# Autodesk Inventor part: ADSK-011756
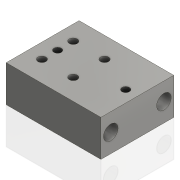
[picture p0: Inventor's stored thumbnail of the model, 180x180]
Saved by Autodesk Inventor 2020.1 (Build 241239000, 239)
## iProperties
Created: 1999-11
Part Number: ADSK-011756
Material: Aluminum
Document SubType Name: Modeling
Designer: sspink
Density: 2.71 g/cm^3
Appearance: Steel
Mass: 1502.63 g
Surface Area: 704.066 cm^2
Volume: 554.478 cm^3
Control State: 0
Master: False
Checked Out: False
Shininess: 0.0
Length Units: 11269
Angle Units: 11279
Time Units: 11290
Mass Units: 11283
Length Display Precision: 3
Angle Display Precision: 2
Compacted: True
Dimensions: 130x50x100 mm
Mass: 1,503 kg
Density: 0.0
Volumn: 0.0
Area: 0.0
PropertySet Name: Model Information
Author: sspink
Revision Number: -
Title: ADSK-011756
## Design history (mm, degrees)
node "Solide1"
  node "Extrusion1" dims "d2" = 100 (= F), "d3" = 0
  node "Hole2" dims "d26" = 6.4008, "d27" = 9.525, "d28" = 6.35, "d29" = 60 deg, "d30" = 25 (= 0.5 x L), "d31" = 118 deg
  node "Hole3" dims "d32" = 6.6, "d33" = 11, "d34" = 6.8, "d35" = 60 deg, "d36" = 12.7, "d37" = 118 deg, "d82" = 6
  node "Extrusion2" dims "d61" = 57.15, "d62" = 0
  node "Hole7" dims "d75" = 10.106, "d76" = 9.525, "d77" = 6.35, "d78" = 60 deg, "d79" = 32.3, "d80" = 118 deg, "d83" = 24
sketch "Sketch1"
  geometry: L1 (-101.574, -4.517)-(28.426, -4.517) reference; L2 (28.426, -4.517)-(28.426, 45.483) reference; L3 (28.426, 45.483)-(-101.574, 45.483); L4 (-101.574, 45.483)-(-101.574, -4.517)
  constraints: 8 end point, 2 horizontal, 2 parallel, 1 perpendicular, 1 vertical
  dimensions: "d0" = 130 distance of L1.start L1.end (= A + Travel); "d1" = 50 distance of L1.end L2.end (= L)
sketch "Sketch3"
  geometry: L1 (0, 0)-(0, 100) reference; L2 (130, 0)-(130, 100) reference; L3 (0, 50)-(130, 50); 4 further points
  constraints: 2 end point, 2 midpoint
  dimensions: "d18" = 20.5 distance from line of point (20.5, 71.5) L1 (= B); "d19" = 20.5 distance from line of point (20.5, 28.5) L1 (= B); "d20" = 43 distance of point (63.5, 28.5) point (20.5, 28.5) (= C); "d21" = 43 distance of point (20.5, 71.5) point (63.5, 71.5) (= C); "d22" = 21.5 distance from line of point (63.5, 71.5) L3 (= 0.5 x C); "d23" = 21.5 distance from line of L3 point (63.5, 28.5) (= 0.5 x C); "d24" = 21.5 distance from line of L3 point (20.5, 28.5) (= 0.5 x C); "d25" = 21.5 distance from line of point (20.5, 71.5) L3 (= 0.5 x C)
node "Corps solides"
node "Corps surfaciques"
sketch "Sketch4"
  geometry: C1 r 3.2 at (20.5, -28.5) reference; C2 r 3.2 at (63.5, -28.5) reference; C3 r 3.2 at (63.5, -71.5) reference; C4 r 3.2 at (20.5, -71.5) reference; 4 further points
  constraints: 4 coincident
sketch "Sketch7"
  geometry: L1 (0, 50)-(100, 50) reference; L2 (0, 0)-(100, 0) reference; L3 (50, 50)-(50, 0); C1 r 10 at (86.5, 25.4); C2 r 10 at (13.5, 25.4)
  constraints: 2 centre point, 2 end point, 2 midpoint, 1 equal radius, 1 horizontal alignment
  dimensions: "d58" = 36.5 distance from line of L3 C2.centre (= 0.5 x W0); "d59" = 36.5 distance from line of L3 C1.centre (= 0.5 x W0); "d60" = 20 diameter of C2 (= X); "d81" = 25.4 distance from line of C2.centre L2 (= D)
sketch "Sketch9"
  geometry: L1 (130, 0)-(130, -100) reference; L2 (0, 0)-(0, -100) reference; L3 (0, -50)-(130, -50); 2 further points
  constraints: 2 end point, 2 midpoint, 2 point on line
  dimensions: "d73" = 20.5 distance from line of point (20.5, -50) L2 (= N_1); "d74" = 16 distance from line of L1 point (114, -50) (= R)
other parameters: "A" = 54 [user parameter; used in 1 equation term], "B" = 20.5 [user parameter; used in 2 equation terms], "C" = 43 [user parameter; used in 6 equation terms], "D" = 25.4 [user parameter; used in 1 equation term], "E0" = 25.4 [user parameter], "G" = 25 [user parameter], "H" = 25 [user parameter], "J0" = 25 [user parameter], "K_1" = 25 [user parameter], "L" = 50 [user parameter; used in 2 equation terms], "M" = 25.4 [user parameter], "N_1" = 20.5 [user parameter; used in 1 equation term], "O" = 25 [user parameter], "P" = 25 [user parameter], "Q" = 6 [user parameter], "R" = 16 [user parameter; used in 1 equation term], "S" = 25 [user parameter], "T" = 25 [user parameter], "U" = 25 [user parameter], "V" = 25 [user parameter], "W0" = 73 [user parameter; used in 2 equation terms], "X" = 20 [user parameter; used in 1 equation term], "Y" = 22 [user parameter], "Z" = 25 [user parameter], "AA" = 25 [user parameter], "CC" = 25.4 [user parameter], "DD" = 25.4 [user parameter], "EE" = 25.4 [user parameter], "FF" = 25.4 [user parameter], "Travel" = 76 [user parameter; used in 1 equation term]
